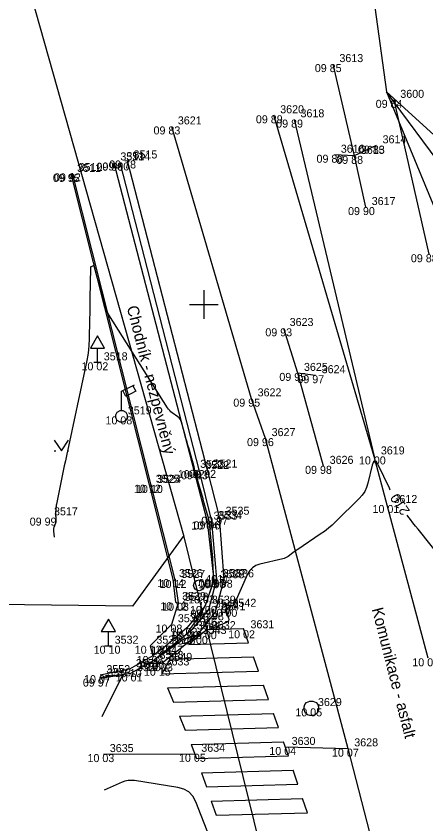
# Model space of a CAD drawing. Extents: x -703403 to -701924, y -1022520 to -1021856.
# Drawn here: x -702681.56 to -702667.24, y -1022343.16 to -1022314.91 of the extents above; entities that cross this region are included whole.
import ezdxf

# ---------------------------------------------------------------- set-up
doc = ezdxf.new("R2010")
doc.units = 0
for name, color, linetype in [('Ex_Contour Labels', 7, 'Continuous'), ('Ex_Major Contours', 7, 'Continuous'), ('Z_bodove_pole', 7, 'Continuous'), ('Z_bodove_pole_cisla', 7, 'Continuous'), ('Z_bodove_pole_vysky', 7, 'Continuous'), ('Z_body', 7, 'Continuous'), ('Z_body_cisla', 7, 'Continuous'), ('Z_body_vysky_redukovane', 7, 'Continuous'), ('Z_chodnik', 7, 'Continuous'), ('Z_dopravni_znacky', 7, 'Continuous'), ('Z_hektometricka_sit', 7, 'Continuous'), ('Z_katastr_hranice', 7, 'Continuous'), ('Z_komunikace', 7, 'Continuous'), ('Z_komunikace_osa', 7, 'Continuous'), ('Z_obruba', 7, 'Continuous'), ('Z_popisy', 7, 'Continuous'), ('Z_rozhranni', 7, 'Continuous'), ('Z_site_kanalizace_znaky', 7, 'Continuous'), ('Z_site_vo_znaky', 7, 'Continuous'), ('Z_vdz13_plna', 7, 'Continuous'), ('Z_vdz13_prerusovana', 7, 'Continuous'), ('Z_VDZ_25_plna', 7, 'Continuous'), ('Z_VDZ_25_prerus', 7, 'Continuous'), ('Z_vdz_prechod', 7, 'Continuous'), ('Z_VDZ_sipky', 7, 'Continuous'), ('Z_znaky_kultur', 7, 'Continuous')]:
    doc.layers.add(name, color=color, linetype=linetype)

# ---------------------------------------------------------------- blocks, each defined once
blk = doc.blocks.new('POINT_DISPLAY')
blk.add_line((0, 0), (0, 0))
blk = doc.blocks.new('Z13')
for p, q in [((0, 0.88), (0.45, 1.1)), ((0, 0.2), (0, 0.88)), ((0.15, 0.7), (0.05, 0.9)), ((0.5, 0.88), (0.15, 0.7)), ((0.4, 1.07), (0.5, 0.88)), ((-0.2, 0.05), (-0.15, 0.15)), ((-0.2, -0.05), (-0.2, 0.05)), ((-0.15, 0.15), (-0.05, 0.2)), ((-0.05, 0.2), (0.05, 0.2)), ((0.05, 0.2), (0.15, 0.15)), ((0.15, 0.15), (0.2, 0.05)), ((0.2, 0.05), (0.2, -0.05)), ((-0.15, -0.15), (-0.2, -0.05)), ((-0.05, -0.2), (-0.15, -0.15)), ((0.05, -0.2), (-0.05, -0.2)), ((0.15, -0.15), (0.05, -0.2)), ((0.2, -0.05), (0.15, -0.15))]:
    blk.add_line(p, q)
blk = doc.blocks.new('Z620')
for p, q in [((-0.25, 0.05), (-0.23, 0.13)), ((-0.25, -0.05), (-0.25, 0.05)), ((-0.23, 0.13), (-0.17, 0.2)), ((-0.17, 0.2), (-0.05, 0.25)), ((-0.05, 0.25), (0.05, 0.25)), ((0.05, 0.25), (0.17, 0.2)), ((0.17, 0.2), (0.23, 0.13)), ((0.23, 0.13), (0.25, 0.05)), ((0.25, 0.05), (0.25, -0.05)), ((-0.2, -0.17), (-0.25, -0.05)), ((-0.13, -0.23), (-0.2, -0.17)), ((-0.05, -0.25), (-0.13, -0.23)), ((0.05, -0.25), (-0.05, -0.25)), ((0.13, -0.23), (0.05, -0.25)), ((0.2, -0.17), (0.13, -0.23)), ((0.25, -0.05), (0.2, -0.17))]:
    blk.add_line(p, q)
blk = doc.blocks.new('Z46260')
for p, q in [((0.13, 0.13), (-0.13, 0.13)), ((-0.13, 0.13), (-0.13, -0.13)), ((0.13, 0), (-0.13, 0)), ((0.13, -0.13), (0.13, 0.13)), ((-0.13, -0.13), (0.13, -0.13))]:
    blk.add_line(p, q)
blk = doc.blocks.new('Z527')
for p, q in [((0, 0.93), (-0.25, 0.5)), ((0.25, 0.5), (0, 0.93)), ((-0.25, 0.5), (0.25, 0.5)), ((0, 0), (0, 0.5)), ((-0.13, 0), (0.13, 0))]:
    blk.add_line(p, q)
blk = doc.blocks.new('Z314')
for p, q in [((-0.25, 0.17), (0, -0.2)), ((0, -0.2), (0.25, 0.17)), ((-0.25, -0.2), (-0.2, -0.2)), ((0.2, -0.2), (0.25, -0.2))]:
    blk.add_line(p, q)
blk = doc.blocks.new('Z101')
for radius in [0.188, 0.0025]:
    blk.add_circle((0, 0), radius)

msp = doc.modelspace()

# ---------------------------------------------------------------- linework, layer by layer
at = {"layer": 'Ex_Major Contours'}
for points in [[(-702668.48, -1022331.491), (-702668.513, -1022331.426), (-702668.904, -1022330.599), (-702668.968, -1022330.492), (-702669.024, -1022330.46), (-702669.073, -1022330.503), (-702669.114, -1022330.621), (-702669.263, -1022331.243), (-702669.309, -1022331.393), (-702669.375, -1022331.532), (-702669.46, -1022331.66), (-702669.564, -1022331.778), (-702670.387, -1022332.591), (-702670.514, -1022332.711), (-702670.647, -1022332.825), (-702670.785, -1022332.932), (-702670.929, -1022333.033), (-702671.719, -1022333.561), (-702671.762, -1022333.59), (-702671.805, -1022333.62), (-702671.847, -1022333.651), (-702671.889, -1022333.682), (-702672.056, -1022333.807), (-702672.099, -1022333.836), (-702672.145, -1022333.86), (-702672.192, -1022333.879), (-702672.242, -1022333.894), (-702673.045, -1022334.08), (-702673.185, -1022334.128), (-702673.303, -1022334.203), (-702673.398, -1022334.305), (-702673.472, -1022334.433), (-702673.913, -1022335.433), (-702673.932, -1022335.467), (-702673.955, -1022335.495), (-702673.983, -1022335.519), (-702674.016, -1022335.539), (-702674.159, -1022335.606), (-702674.189, -1022335.626), (-702674.207, -1022335.65), (-702674.213, -1022335.68), (-702674.207, -1022335.716), (-702674.133, -1022335.966), (-702674.125, -1022336.016), (-702674.134, -1022336.058), (-702674.161, -1022336.092), (-702674.205, -1022336.118), (-702674.868, -1022336.387), (-702674.909, -1022336.404), (-702674.949, -1022336.422), (-702674.988, -1022336.442), (-702675.028, -1022336.463), (-702675.182, -1022336.548), (-702675.222, -1022336.567), (-702675.262, -1022336.585), (-702675.303, -1022336.6), (-702675.346, -1022336.612), (-702675.609, -1022336.678), (-702675.666, -1022336.695), (-702675.72, -1022336.718), (-702675.772, -1022336.745), (-702675.822, -1022336.778), (-702676.509, -1022337.272), (-702676.607, -1022337.342), (-702676.642, -1022337.362), (-702676.613, -1022337.334), (-702676.52, -1022337.257), (-702675.57, -1022336.488), (-702675.562, -1022336.481), (-702675.555, -1022336.472), (-702675.549, -1022336.463), (-702675.544, -1022336.453), (-702675.528, -1022336.411), (-702675.524, -1022336.401), (-702675.519, -1022336.391), (-702675.513, -1022336.381), (-702675.506, -1022336.372), (-702675.295, -1022336.09), (-702675.258, -1022336.04), (-702675.223, -1022335.988), (-702675.189, -1022335.936), (-702675.156, -1022335.883), (-702675.018, -1022335.653), (-702674.985, -1022335.596), (-702674.957, -1022335.537), (-702674.931, -1022335.477), (-702674.909, -1022335.416), (-702674.721, -1022334.854), (-702674.691, -1022334.746), (-702674.671, -1022334.637), (-702674.661, -1022334.527), (-702674.662, -1022334.415), (-702674.685, -1022333.964), (-702674.692, -1022333.851), (-702674.699, -1022333.739), (-702674.708, -1022333.626), (-702674.718, -1022333.514), (-702674.79, -1022332.749), (-702674.799, -1022332.668), (-702674.812, -1022332.586), (-702674.829, -1022332.506), (-702674.85, -1022332.426), (-702674.94, -1022332.109), (-702674.963, -1022332.029), (-702674.985, -1022331.95), (-702675.008, -1022331.871), (-702675.03, -1022331.791), (-702675.24, -1022331.045), (-702675.275, -1022330.922), (-702675.31, -1022330.799), (-702675.344, -1022330.675), (-702675.379, -1022330.552), (-702675.529, -1022330.015), (-702675.557, -1022329.914), (-702675.586, -1022329.812), (-702675.614, -1022329.71), (-702675.643, -1022329.608), (-702675.784, -1022329.113), (-702675.804, -1022329.059), (-702675.833, -1022329.009), (-702675.869, -1022328.966), (-702675.913, -1022328.927), (-702676.106, -1022328.785), (-702676.152, -1022328.748), (-702676.194, -1022328.706), (-702676.232, -1022328.662), (-702676.266, -1022328.613), (-702678.32, -1022325.362), (-702678.352, -1022325.307), (-702678.38, -1022325.251), (-702678.404, -1022325.192), (-702678.423, -1022325.132), (-702678.494, -1022324.888), (-702678.512, -1022324.827), (-702678.53, -1022324.766), (-702678.547, -1022324.705), (-702678.564, -1022324.643), (-702678.835, -1022323.661), (-702678.841, -1022323.647), (-702678.85, -1022323.64), (-702678.861, -1022323.638), (-702678.875, -1022323.643), (-702678.938, -1022323.675), (-702678.952, -1022323.685), (-702678.962, -1022323.696), (-702678.968, -1022323.71), (-702678.97, -1022323.727), (-702678.982, -1022324.776), (-702678.984, -1022324.956), (-702678.987, -1022325.137), (-702678.99, -1022325.318), (-702678.995, -1022325.498), (-702679.012, -1022326.23), (-702679.021, -1022326.412), (-702679.038, -1022326.593), (-702679.063, -1022326.772), (-702679.097, -1022326.951), (-702679.805, -1022330.286), (-702679.842, -1022330.463), (-702679.88, -1022330.64), (-702679.917, -1022330.817), (-702679.953, -1022330.994), (-702680.158, -1022331.982), (-702680.165, -1022332.019), (-702680.17, -1022332.057), (-702680.174, -1022332.095), (-702680.177, -1022332.133), (-702680.184, -1022332.303), (-702680.185, -1022332.332), (-702680.185, -1022332.362), (-702680.184, -1022332.391), (-702680.182, -1022332.419), (-702680.173, -1022332.535), (-702680.173, -1022332.564), (-702680.175, -1022332.592), (-702680.18, -1022332.62), (-702680.189, -1022332.648), (-702680.243, -1022332.791), (-702680.253, -1022332.825), (-702680.259, -1022332.858), (-702680.261, -1022332.892), (-702680.258, -1022332.927), (-702680.231, -1022333.139)], [(-702665.422, -1022335.48), (-702667.51, -1022332.859), (-702667.6, -1022332.744), (-702667.69, -1022332.628), (-702667.779, -1022332.512), (-702667.866, -1022332.395), (-702667.891, -1022332.361)], [(-702678.555, -1022339.4), (-702677.888, -1022338.067), (-702677.87, -1022338.014), (-702677.877, -1022337.979), (-702677.907, -1022337.961), (-702677.963, -1022337.96), (-702678.309, -1022337.997), (-702678.339, -1022338.001), (-702678.369, -1022338.005), (-702678.399, -1022338.009), (-702678.429, -1022338.014), (-702678.609, -1022338.044)], [(-702674.798, -1022343.619), (-702675.286, -1022342.385), (-702675.389, -1022342.193), (-702675.527, -1022342.045), (-702675.702, -1022341.943), (-702675.912, -1022341.885), (-702677.431, -1022341.649), (-702677.542, -1022341.639), (-702677.651, -1022341.646), (-702677.758, -1022341.668), (-702677.862, -1022341.707), (-702678.484, -1022341.984)]]:
    msp.add_lwpolyline(points, dxfattribs=at)
at = {"layer": 'Z_chodnik'}
for p, q in [((-702679.61, -1022320.41), (-702676.86, -1022331.31)), ((-702676.86, -1022331.31), (-702676.01, -1022334.63)), ((-702676.01, -1022334.63), (-702675.9, -1022335.43)), ((-702675.9, -1022335.43), (-702676.13, -1022336.19)), ((-702676.13, -1022336.19), (-702676.88, -1022336.93)), ((-702676.88, -1022336.93), (-702676.79, -1022337.29))]:
    msp.add_line(p, q, dxfattribs=at)
at = {"layer": 'Z_hektometricka_sit'}
for p, q in [((-702675, -1022324.5), (-702675, -1022325.5)), ((-702675.5, -1022325), (-702674.5, -1022325))]:
    msp.add_line(p, q, dxfattribs=at)
at = {"layer": 'Z_katastr_hranice'}
for p, q in [((-702675.7, -1022333.08), (-702691.716, -1022276.344)), ((-702671.1, -1022299.73), (-702668.61, -1022317.56)), ((-702668.61, -1022317.56), (-702658.75, -1022341.48)), ((-702668.61, -1022317.56), (-702665.72, -1022320.2)), ((-702663.64, -1022324.29), (-702668.61, -1022317.56)), ((-702675.7, -1022333.08), (-702677.5, -1022335.55)), ((-702672.38, -1022346.56), (-702675.7, -1022333.08)), ((-702677.5, -1022335.55), (-702692.553, -1022335.351))]:
    msp.add_line(p, q, dxfattribs=at)
at = {"layer": 'Z_komunikace'}
for p, q in [((-702677.94, -1022320.03), (-702675.17, -1022330.83)), ((-702675.17, -1022330.83), (-702674.73, -1022332.58)), ((-702674.73, -1022332.58), (-702674.56, -1022334.6)), ((-702674.56, -1022334.6), (-702674.84, -1022335.67)), ((-702674.84, -1022335.67), (-702675.48, -1022336.43)), ((-702675.48, -1022336.43), (-702676.77, -1022337.46)), ((-702676.77, -1022337.46), (-702677.57, -1022337.9)), ((-702677.57, -1022337.9), (-702678.6, -1022338.08))]:
    msp.add_line(p, q, dxfattribs=at)
at = {"layer": 'Z_komunikace_osa'}
for p, q in [((-702672.15, -1022340.47), (-702669.96, -1022340.53)), ((-702678.51, -1022340.72), (-702675.31, -1022340.71))]:
    msp.add_line(p, q, dxfattribs=at)
at = {"layer": 'Z_obruba'}
for p, q in [((-702678.15, -1022320.04), (-702675.35, -1022330.79)), ((-702679.65, -1022320.43), (-702676.91, -1022331.3)), ((-702675.35, -1022330.79), (-702674.88, -1022332.59)), ((-702676.91, -1022331.3), (-702676.09, -1022334.6)), ((-702674.88, -1022332.59), (-702674.65, -1022334.64)), ((-702676.09, -1022334.6), (-702675.99, -1022335.41)), ((-702674.65, -1022334.64), (-702674.95, -1022335.54)), ((-702675.99, -1022335.41), (-702675.9, -1022335.43)), ((-702674.95, -1022335.54), (-702675.6, -1022336.31)), ((-702675.6, -1022336.31), (-702676.35, -1022336.96)), ((-702676.35, -1022336.96), (-702676.79, -1022337.29)), ((-702676.79, -1022337.29), (-702677.6, -1022337.75)), ((-702677.6, -1022337.75), (-702678.63, -1022337.96))]:
    msp.add_line(p, q, dxfattribs=at)
at = {"layer": 'Z_rozhranni'}
for p, q in [((-702677.68, -1022319.96), (-702674.88, -1022330.78)), ((-702674.88, -1022330.78), (-702674.46, -1022332.42)), ((-702674.46, -1022332.42), (-702674.3, -1022334.62)), ((-702674.3, -1022334.62), (-702674.61, -1022335.76)), ((-702674.61, -1022335.76), (-702675.26, -1022336.59)), ((-702675.26, -1022336.59), (-702676.46, -1022337.54)), ((-702676.46, -1022337.54), (-702676.77, -1022337.46))]:
    msp.add_line(p, q, dxfattribs=at)
at = {"layer": 'Z_vdz13_plna'}
for p, q in [((-702669.04, -1022330.31), (-702672.55, -1022318.38)), ((-702671.84, -1022318.53), (-702669.04, -1022330.31))]:
    msp.add_line(p, q, dxfattribs=at)
at = {"layer": 'Z_vdz13_prerusovana'}
for p, q in [((-702668.59, -1022332.01), (-702669.04, -1022330.31)), ((-702667.15, -1022337.37), (-702668.59, -1022332.01))]:
    msp.add_line(p, q, dxfattribs=at)
at = {"layer": 'Z_VDZ_25_plna'}
for p, q in [((-702668.36, -1022317.84), (-702667.13, -1022323.24)), ((-702676.13, -1022318.77), (-702673.34, -1022328.29))]:
    msp.add_line(p, q, dxfattribs=at)
at = {"layer": 'Z_VDZ_25_prerus'}
for p, q in [((-702673.34, -1022328.29), (-702672.86, -1022329.67)), ((-702672.86, -1022329.67), (-702669.96, -1022340.53)), ((-702669.96, -1022340.53), (-702668.28, -1022347.09))]:
    msp.add_line(p, q, dxfattribs=at)
at = {"layer": 'Z_vdz_prechod'}
for p, q in [((-702674.881, -1022336.365), (-702675.534, -1022336.884)), ((-702674.881, -1022336.365), (-702673.611, -1022336.329)), ((-702673.437, -1022336.825), (-702673.611, -1022336.329)), ((-702675.534, -1022336.884), (-702673.437, -1022336.825)), ((-702676.186, -1022337.403), (-702676.472, -1022337.911)), ((-702676.186, -1022337.403), (-702673.262, -1022337.32)), ((-702673.087, -1022337.815), (-702673.262, -1022337.32)), ((-702676.472, -1022337.911), (-702673.087, -1022337.815)), ((-702676.267, -1022338.405), (-702672.912, -1022338.311)), ((-702672.737, -1022338.806), (-702672.912, -1022338.311)), ((-702676.267, -1022338.405), (-702676.062, -1022338.9)), ((-702676.062, -1022338.9), (-702672.737, -1022338.806)), ((-702675.856, -1022339.394), (-702672.563, -1022339.301)), ((-702675.856, -1022339.394), (-702675.651, -1022339.889)), ((-702672.388, -1022339.796), (-702672.563, -1022339.301)), ((-702675.651, -1022339.889), (-702672.388, -1022339.796)), ((-702675.446, -1022340.383), (-702672.213, -1022340.292)), ((-702672.044, -1022340.787), (-702672.213, -1022340.292)), ((-702675.446, -1022340.383), (-702675.252, -1022340.878)), ((-702675.252, -1022340.878), (-702672.044, -1022340.787)), ((-702675.082, -1022341.373), (-702671.878, -1022341.282)), ((-702675.082, -1022341.373), (-702674.912, -1022341.868)), ((-702671.713, -1022341.778), (-702671.878, -1022341.282)), ((-702674.912, -1022341.868), (-702671.713, -1022341.778)), ((-702674.741, -1022342.364), (-702671.547, -1022342.273)), ((-702671.381, -1022342.769), (-702671.547, -1022342.273)), ((-702674.741, -1022342.364), (-702674.571, -1022342.859)), ((-702674.571, -1022342.859), (-702671.381, -1022342.769))]:
    msp.add_line(p, q, dxfattribs=at)
at = {"layer": 'Z_VDZ_sipky'}
for p, q in [((-702670.49, -1022316.59), (-702669.74, -1022319.8)), ((-702668.98, -1022319.44), (-702669.74, -1022319.8)), ((-702669.74, -1022319.8), (-702670.43, -1022319.76)), ((-702669.74, -1022319.8), (-702669.35, -1022321.59)), ((-702672.22, -1022325.83), (-702671.73, -1022327.39)), ((-702671.73, -1022327.39), (-702671.1, -1022327.47)), ((-702671.73, -1022327.39), (-702670.83, -1022330.64))]:
    msp.add_line(p, q, dxfattribs=at)

# ---------------------------------------------------------------- block references
at = {"layer": 'Z_bodove_pole'}
msp.add_blockref('Z101', (-702675.17, -1022334.82), dxfattribs=at)
at = {"layer": 'Z_body'}
for p in [(-702670.49, -1022316.59), (-702668.36, -1022317.84), (-702672.55, -1022318.38), (-702671.84, -1022318.53), (-702676.13, -1022318.77), (-702668.98, -1022319.44), (-702670.43, -1022319.76), (-702678.15, -1022320.04), (-702677.94, -1022320.03), (-702677.68, -1022319.96), (-702669.74, -1022319.8), (-702679.65, -1022320.43), (-702679.61, -1022320.41), (-702669.35, -1022321.59), (-702672.22, -1022325.83), (-702678.72, -1022327.02), (-702671.73, -1022327.39), (-702671.1, -1022327.47), (-702673.34, -1022328.29), (-702677.88, -1022328.91), (-702672.86, -1022329.67), (-702669.04, -1022330.31), (-702670.83, -1022330.64), (-702675.35, -1022330.79), (-702675.17, -1022330.83), (-702674.88, -1022330.78), (-702676.91, -1022331.3), (-702676.86, -1022331.31), (-702668.59, -1022332.01), (-702680.46, -1022332.45), (-702674.46, -1022332.42), (-702674.88, -1022332.59), (-702674.73, -1022332.58), (-702676.09, -1022334.6), (-702676.01, -1022334.63), (-702674.65, -1022334.64), (-702674.56, -1022334.6), (-702674.3, -1022334.62), (-702675.17, -1022334.82), (-702675.99, -1022335.41), (-702675.9, -1022335.43), (-702674.95, -1022335.54), (-702674.84, -1022335.67), (-702674.61, -1022335.76), (-702674.23, -1022335.64), (-702676.13, -1022336.19), (-702675.6, -1022336.31), (-702674.95, -1022336.42), (-702673.59, -1022336.39), (-702675.48, -1022336.43), (-702675.26, -1022336.59), (-702678.34, -1022336.93), (-702676.88, -1022336.93), (-702676.35, -1022336.96), (-702676.79, -1022337.29), (-702676.77, -1022337.46), (-702676.46, -1022337.54), (-702677.6, -1022337.75), (-702676.56, -1022337.7), (-702678.63, -1022337.96), (-702678.6, -1022338.08), (-702677.57, -1022337.9), (-702671.24, -1022339.12), (-702672.15, -1022340.47), (-702669.96, -1022340.53), (-702678.51, -1022340.72), (-702675.31, -1022340.71)]:
    msp.add_blockref('POINT_DISPLAY', p, dxfattribs=at)
at = {"layer": 'Z_dopravni_znacky'}
for p in [(-702678.72, -1022327.02), (-702678.34, -1022336.93)]:
    msp.add_blockref('Z527', p, dxfattribs=at)
at = {"layer": 'Z_site_kanalizace_znaky', "rotation": 74.7}
msp.add_blockref('Z46260', (-702674.23, -1022335.64), dxfattribs=at)
at = {"layer": 'Z_site_kanalizace_znaky'}
msp.add_blockref('Z620', (-702671.24, -1022339.12), dxfattribs=at)
at = {"layer": 'Z_site_vo_znaky'}
msp.add_blockref('Z13', (-702677.88, -1022328.91), dxfattribs=at)
at = {"layer": 'Z_znaky_kultur'}
msp.add_blockref('Z314', (-702679.98, -1022329.91), dxfattribs=at)

# ---------------------------------------------------------------- texts
at = {"layer": 'Ex_Contour Labels'}
msp.add_text('210', height=0.35, rotation=124.1094, dxfattribs=at).set_placement((-702667.78, -1022332.214))
at = {"layer": 'Z_bodove_pole_cisla'}
msp.add_text('4011', height=0.28, dxfattribs=at).set_placement((-702674.95, -1022334.74))
at = {"layer": 'Z_bodove_pole_vysky'}
msp.add_text('210,03', height=0.28, dxfattribs=at).set_placement((-702675.76, -1022335.45))
at = {"layer": 'Z_body_cisla'}
for s, p in [('3613', (-702670.26, -1022316.52)), ('3600', (-702668.13, -1022317.77)), ('3620', (-702672.33, -1022318.31)), ('3618', (-702671.62, -1022318.45)), ('3621', (-702675.91, -1022318.7)), ('3614', (-702668.75, -1022319.36)), ('3616', (-702670.21, -1022319.69)), ('3615', (-702669.51, -1022319.73)), ('3513', (-702677.92, -1022319.96)), ('3514', (-702677.71, -1022319.95)), ('3515', (-702677.46, -1022319.89)), ('3511', (-702679.43, -1022320.36)), ('3512', (-702679.38, -1022320.33)), ('3617', (-702669.13, -1022321.52)), ('3623', (-702672, -1022325.75)), ('3518', (-702678.5, -1022326.95)), ('3625', (-702671.5, -1022327.32)), ('3624', (-702670.88, -1022327.4)), ('3622', (-702673.12, -1022328.21)), ('3519', (-702677.66, -1022328.84)), ('3627', (-702672.63, -1022329.6)), ('3619', (-702668.81, -1022330.24)), ('3523', (-702675.13, -1022330.71)), ('3522', (-702674.95, -1022330.75)), ('3521', (-702674.66, -1022330.7)), ('3626', (-702670.6, -1022330.57)), ('3525', (-702676.68, -1022331.23)), ('3524', (-702676.63, -1022331.24)), ('3612', (-702668.37, -1022331.94)), ('3517', (-702680.24, -1022332.37)), ('3535', (-702674.24, -1022332.35)), ('3533', (-702674.66, -1022332.52)), ('3534', (-702674.5, -1022332.5)), ('3526', (-702675.87, -1022334.53)), ('3527', (-702675.79, -1022334.56)), ('3538', (-702674.42, -1022334.57)), ('3537', (-702674.34, -1022334.53)), ('3536', (-702674.08, -1022334.54)), ('3529', (-702675.76, -1022335.33)), ('3528', (-702675.67, -1022335.36)), ('3539', (-702674.72, -1022335.46)), ('3542', (-702674, -1022335.57)), ('3540', (-702674.62, -1022335.6)), ('3541', (-702674.38, -1022335.69)), ('3530', (-702675.91, -1022336.11)), ('3545', (-702675.38, -1022336.24)), ('3544', (-702675.25, -1022336.36)), ('3632', (-702674.72, -1022336.35)), ('3631', (-702673.37, -1022336.32)), ('3543', (-702675.04, -1022336.52)), ('3532', (-702678.12, -1022336.86)), ('3531', (-702676.66, -1022336.86)), ('3546', (-702676.13, -1022336.89)), ('3547', (-702676.56, -1022337.21)), ('3548', (-702676.55, -1022337.39)), ('3549', (-702676.24, -1022337.46)), ('3551', (-702677.38, -1022337.68)), ('3550', (-702677.34, -1022337.82)), ('3633', (-702676.34, -1022337.62)), ('3552', (-702678.41, -1022337.89)), ('3553', (-702678.38, -1022338)), ('3629', (-702671.01, -1022339.04)), ('3635', (-702678.29, -1022340.65)), ('3634', (-702675.09, -1022340.64)), ('3630', (-702671.93, -1022340.4)), ('3628', (-702669.74, -1022340.45))]:
    msp.add_text(s, height=0.28, dxfattribs=at).set_placement(p)
at = {"layer": 'Z_body_vysky_redukovane'}
for s, p in [('09 85', (-702671.12, -1022316.87)), ('09 84', (-702668.99, -1022318.12)), ('09 89', (-702673.18, -1022318.66)), ('09 89', (-702672.47, -1022318.81)), ('09 83', (-702676.76, -1022319.05)), ('09 83', (-702669.61, -1022319.72)), ('09 88', (-702671.06, -1022320.04)), ('09 90', (-702678.757, -1022320.32)), ('09 80', (-702678.547, -1022320.31)), ('09 78', (-702678.31, -1022320.24)), ('09 88', (-702670.37, -1022320.08)), ('09 95', (-702680.28, -1022320.71)), ('09 92', (-702680.24, -1022320.69)), ('09 90', (-702669.957, -1022321.87)), ('09 88', (-702667.76, -1022323.52)), ('09 93', (-702672.85, -1022326.11)), ('10 02', (-702679.28, -1022327.3)), ('09 95', (-702672.36, -1022327.67)), ('09 97', (-702671.73, -1022327.75)), ('09 95', (-702673.97, -1022328.57)), ('10 08', (-702678.44, -1022329.19)), ('09 96', (-702673.49, -1022329.95)), ('10 00', (-702669.577, -1022330.59)), ('09 92', (-702675.51, -1022331.06)), ('09 98', (-702671.46, -1022330.92)), ('10 02', (-702675.91, -1022331.07)), ('09 93', (-702675.8, -1022331.11)), ('10 12', (-702677.447, -1022331.58)), ('10 10', (-702677.373, -1022331.59)), ('10 01', (-702669.103, -1022332.29)), ('09 99', (-702681.09, -1022332.73)), ('09 97', (-702675.09, -1022332.7)), ('10 04', (-702675.44, -1022332.87)), ('09 96', (-702675.36, -1022332.86)), ('10 14', (-702676.627, -1022334.88)), ('10 12', (-702676.547, -1022334.91)), ('09 97', (-702675.19, -1022334.88)), ('10 00', (-702675.187, -1022334.92)), ('09 98', (-702674.93, -1022334.9)), ('10 12', (-702676.527, -1022335.69)), ('10 08', (-702676.46, -1022335.71)), ('10 00', (-702675.487, -1022335.82)), ('09 98', (-702675.47, -1022335.95)), ('09 98', (-702675.24, -1022336.04)), ('10 00', (-702674.767, -1022335.92)), ('10 08', (-702676.69, -1022336.47)), ('10 02', (-702676.16, -1022336.59)), ('09 99', (-702676.11, -1022336.71)), ('10 00', (-702675.487, -1022336.7)), ('10 02', (-702674.15, -1022336.67)), ('10 00', (-702675.797, -1022336.87)), ('10 10', (-702678.853, -1022337.21)), ('10 12', (-702677.417, -1022337.21)), ('10 11', (-702676.84, -1022337.24)), ('10 08', (-702677.35, -1022337.57)), ('10 00', (-702677.307, -1022337.74)), ('10 03', (-702677.02, -1022337.82)), ('10 08', (-702667.71, -1022337.65)), ('10 10', (-702678.113, -1022338.03)), ('10 15', (-702677.097, -1022337.98)), ('09 97', (-702679.23, -1022338.36)), ('10 07', (-702679.19, -1022338.24)), ('10 01', (-702678.083, -1022338.18)), ('10 05', (-702671.8, -1022339.4)), ('10 04', (-702672.71, -1022340.75)), ('10 07', (-702670.52, -1022340.81)), ('10 03', (-702679.07, -1022341)), ('10 05', (-702675.87, -1022340.99))]:
    msp.add_text(s, height=0.28, dxfattribs=at).set_placement(p)
at = {"layer": 'Z_popisy'}
for s, p in [('Chodník - nezpevněný', (-702677.7, -1022325.09)), ('Komunikace - asfalt', (-702669.13, -1022335.65))]:
    msp.add_text(s, height=0.4, rotation=284.4, dxfattribs=at).set_placement(p)

doc.saveas('drawing.dxf')
